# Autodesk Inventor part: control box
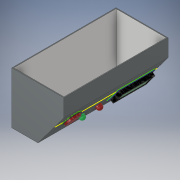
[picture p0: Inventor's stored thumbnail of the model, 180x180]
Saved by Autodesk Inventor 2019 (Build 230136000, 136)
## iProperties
Created: 2021-07
Part Number: control box
Material: Generic
Document SubType Name: Modeling
Designer: Avinash
Density: 1 g/cm^3
Appearance: Default
Author: Avinash
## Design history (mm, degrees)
sketch "Sketch1"
  geometry: L1 (0, 0)-(30, 0); L2 (30, 0)-(59.977, 40.017); L3 (59.977, 40.017)-(59.977, 60.017); L4 (59.977, 60.017)-(0, 60.017); L5 (0, 60.017)-(0, 0)
  constraints: 10 end point, 3 perpendicular, 1 horizontal
  dimensions: "d0" = 30 distance of L1.start L1.end; "d1" = 50 distance of L1.end L2.end; "d2" = 20 distance of L2.end L3.end
extrude "Extrusion1" new body sketch "Sketch1" distance "d3" = 120; taper "d4" = 0 deg
sketch "Sketch2"
  geometry: L1 (111.7, -35.228)-(73.748, -35.228); L2 (73.748, -35.228)-(73.748, -17.731); L3 (73.748, -17.731)-(111.7, -17.731); L4 (111.7, -17.731)-(111.7, -35.228); L5 (71.748, -37.228)-(113.7, -37.228); L6 (113.7, -37.228)-(113.7, -15.731); L7 (113.7, -15.731)-(71.748, -15.731); L8 (71.748, -15.731)-(71.748, -37.228); L9 (109.293, -32.821)-(76.155, -32.821); L10 (76.155, -32.821)-(76.155, -20.139); L11 (76.155, -20.139)-(109.293, -20.139); L12 (109.293, -20.139)-(109.293, -32.821); 1 further point
  constraints: 24 end point, 2 parallel, 1 horizontal, 1 perpendicular
extrude "Extrusion2" join sketch "Sketch2" distance "d5" = 5; taper "d6" = 0 deg
extrude "Extrusion3" join sketch "Sketch2" distance "d7" = 4.5; taper "d8" = 0 deg
shell "Shell1" dims "d9" = 1
extrude "Extrusion4" join sketch "Sketch2" distance "d10" = 1; taper "d11" = 0 deg
sketch "Sketch3"
  geometry: C1 r 3.236 at (60, -34.456); C2 r 3.236 at (40.106, -34.456); 1 further point
  constraints: 2 centre point
extrude "Extrusion5" join sketch "Sketch3" distance "d12" = 5; taper "d13" = 0 deg
fillet "Fillet1" dims "d14" = 3.2
sketch "Sketch4"
  geometry: L1 (1, -19.352)-(119, -19.352) reference; C1 r 9.643 at (20.223, -19.352); C2 r 8.037 at (20.223, -19.352); 1 further point
  constraints: 2 centre point, 1 coincident, 1 point on line
extrude "Extrusion6" join sketch "Sketch4" distance "d15" = 1; taper "d16" = 0 deg
extrude "Extrusion7" join sketch "Sketch4" distance "d17" = 3; taper "d18" = 0 deg
body "Solid1"
